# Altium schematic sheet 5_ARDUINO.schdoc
size 601 x 429 mm; Symbol: Drawing-Symbol_A4; Device: Drawing-Symbol_A4; @Project Name: Slowpoke; @Page Count: 7; @Update Date: 2025-12-15; @Create Date: 2025-12-13; @Schematic Name: Slowpoke_Sch; @Page No: 5; @Page Name: ARDUINO; Company: Analog Devices, Inc.; Version: V1.0; Page Size: A4; @Create Time: 14:28:30; @Update Time: 15:57:42; Width: 2338; Height: 1652; Region Start: 1; X Region Count: 6; Y Region Count: 4; Blade Width: 10; Title Block Position: 3; @Board Name: Slowpoke
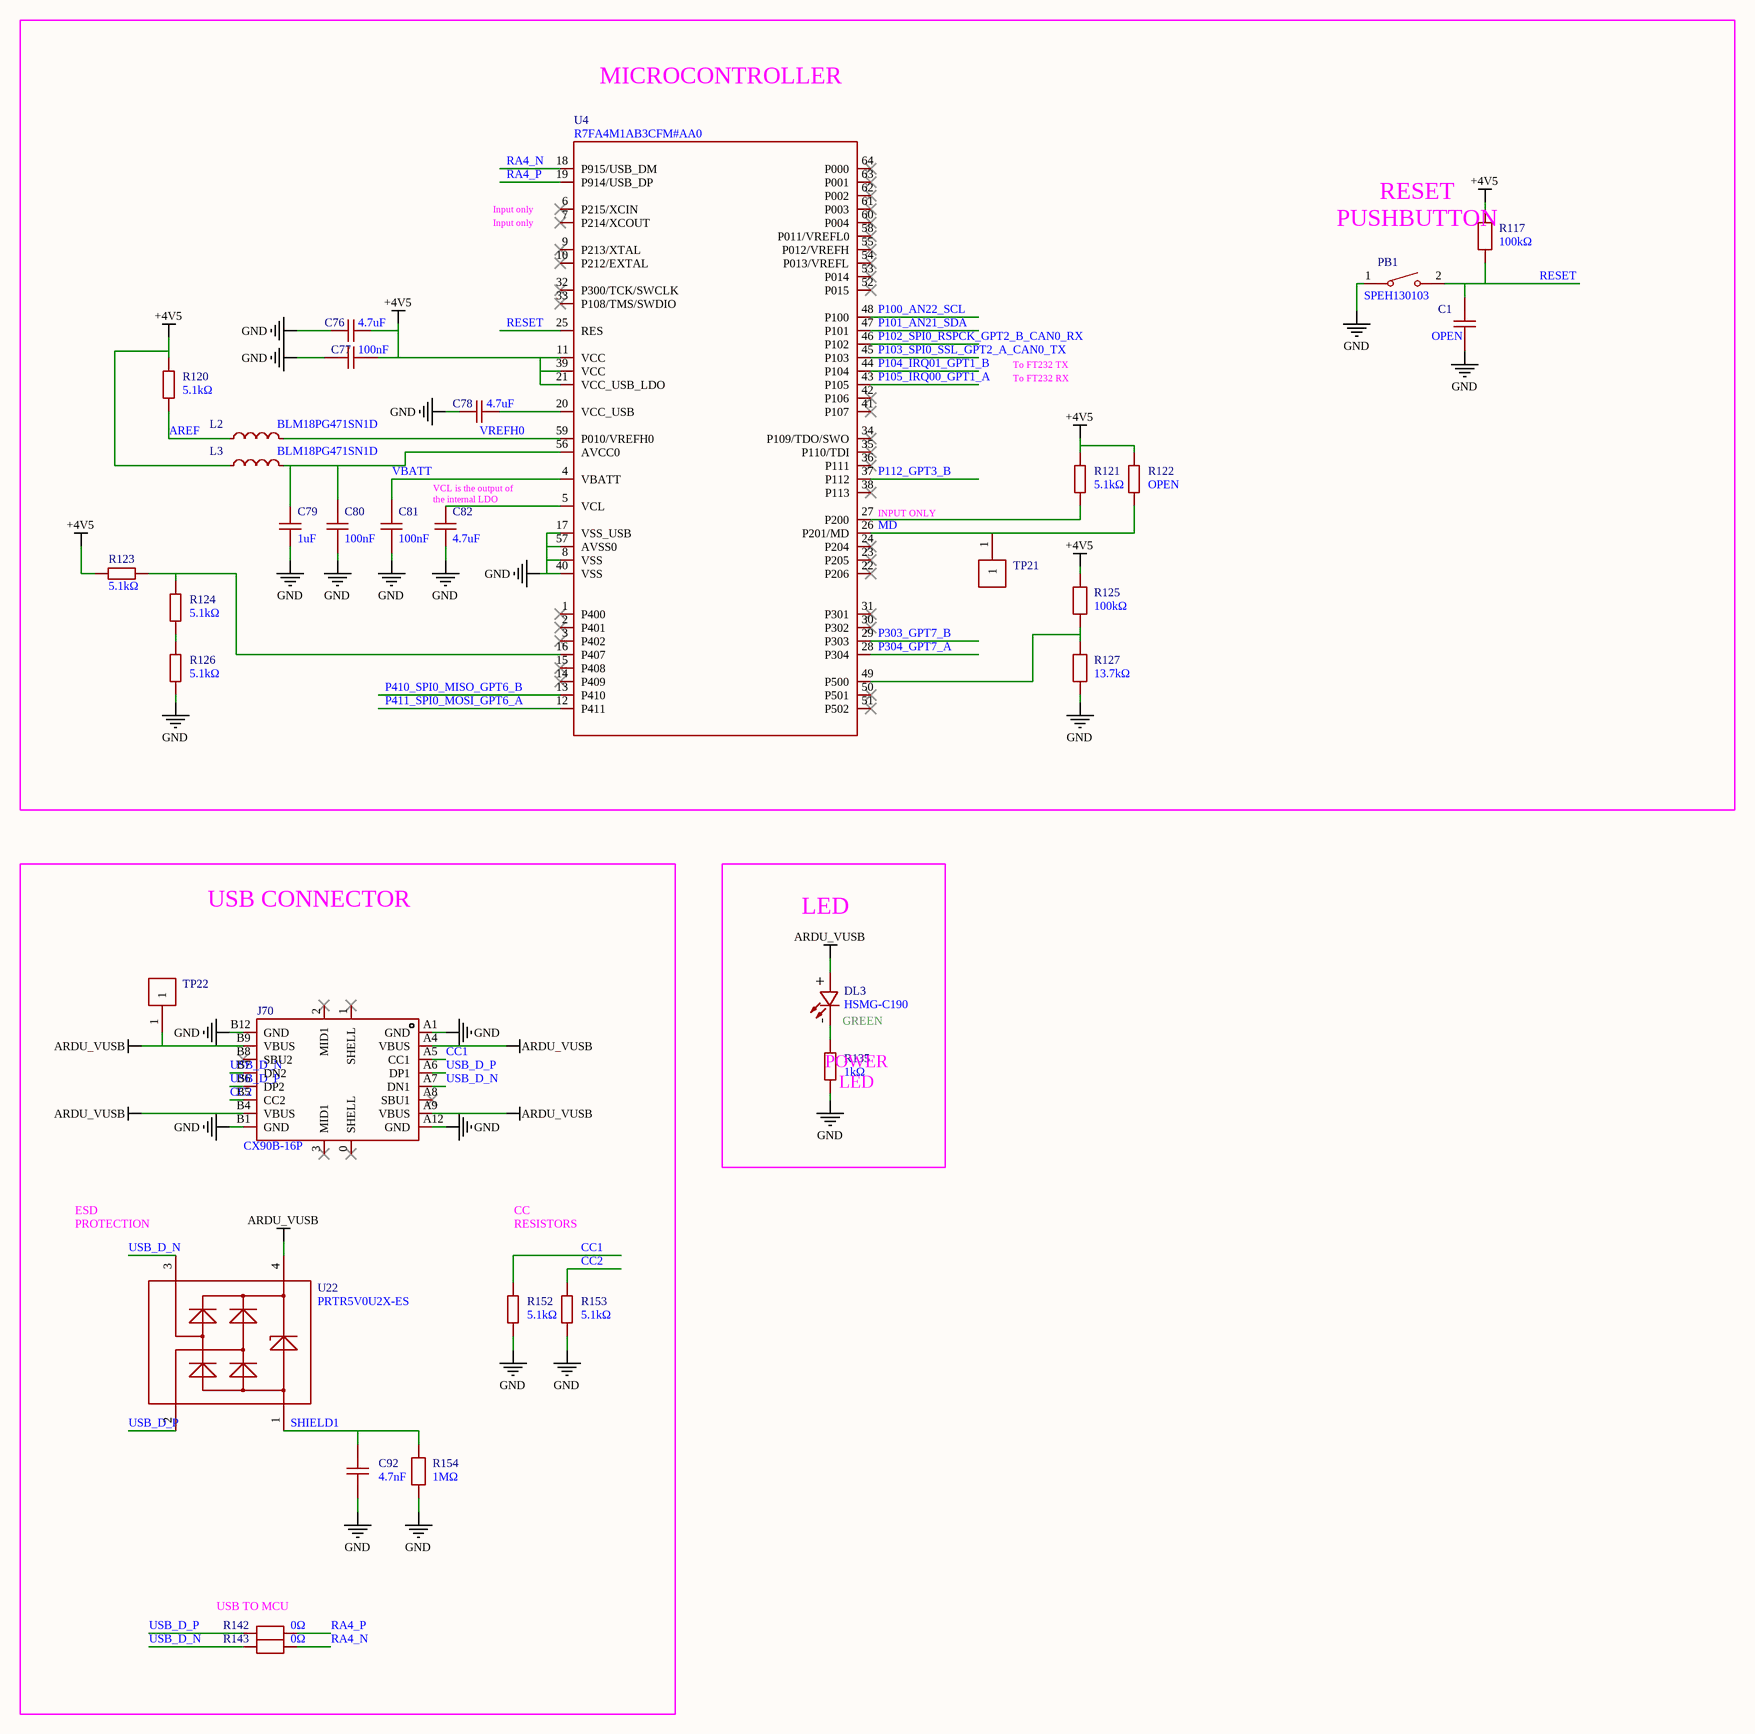
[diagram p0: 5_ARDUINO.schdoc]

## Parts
C1  OPEN  [C0402]
C76  4.7uF  [C0402]
C77  100nF  [C0402]
C78  4.7uF  [C0402]
C79  1uF  [C0402]
C80  100nF  [C0402]
C81  100nF  [C0402]
C82  4.7uF  [C0402]
C92  4.7nF  [C0805]
DL3  HSMG-C190  [LED-SMD_L1.6-W0.8-R-RD]
J70  CX90B-16P  [USB-C-SMD_CX90B-16P]
L2  BLM18PG471SN1D  [L0603]
L3  BLM18PG471SN1D  [L0603]
PB1  SPEH130103  [SW-SMD_L6.0-W6.0-LS6.6]
R117  100kΩ  [R0402]
R120  5.1kΩ  [R0402]
R121  5.1kΩ  [R0402]
R122  OPEN  [R0402]
R123  5.1kΩ  [R0402]
R124  5.1kΩ  [R0402]
R125  100kΩ  [R0402]
R126  5.1kΩ  [R0402]
R127  13.7kΩ  [R0402]
R135  1kΩ  [R0603]
R142  0Ω  [R0402]
R143  0Ω  [R0402]
R152  5.1kΩ  [R0402]
R153  5.1kΩ  [R0402]
R154  1MΩ  [R0402]
TP21  RH-5002  [TESTPOINT-TH_BD2.5-D1.2_RH-5002]  (value not drawn)
TP22  RH-5000  [TEST-TH_BD2.54-P1.4_RED]  (value not drawn)
U4  R7FA4M1AB3CFM#AA0  [LQFP-64_L10.0-W10.0-P0.50-LS12.0-BL]
U22  PRTR5V0U2X-ES  [SOT-143_L2.9-W1.3-P1.92-LS2.3-BR]

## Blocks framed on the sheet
MICROCONTROLLER: C1 C76-C82 L2 L3 PB1 R117 R120-R127 TP21 U4
USB CONNECTOR: C92 J70 R142 R143 R152-R154 TP22 U22
LED: DL3 R135

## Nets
+4V5: C76.2 C77.2 L3.1 R117.2 R120.2 R121.2 R122.2 R123.2 R125.2 U4.11(VCC) U4.21(VCC_USB_LDO) U4.39(VCC)
ARDU_VUSB: DL3.1(A) J70.A4(VBUS) J70.A9(VBUS) J70.B4(VBUS) J70.B9(VBUS) TP22.1 U22.4(VCC)
GND: C1.1 C76.1 C77.1 C78.1 C79.1 C80.1 C81.1 C82.1 C92.1 J70.A1(GND) J70.A12(GND) J70.B1(GND) J70.B12(GND) PB1.1 R126.1 R127.1 R135.1 R152.1 R153.1 R154.1 U4.8(VSS) U4.17(VSS_USB) U4.40(VSS) U4.57(AVSS0)
AREF: L2.1 R120.1
CC1: J70.A5(CC1) R152.2
CC2: J70.B5(CC2) R153.2
MD: R122.1 TP21.1 U4.26(P201/MD)
P100_AN22_SCL: U4.48(P100)
P101_AN21_SDA: U4.47(P101)
P102_SPI0_RSPCK_GPT2_B_CAN0_RX: U4.46(P102)
P103_SPI0_SSL_GPT2_A_CAN0_TX: U4.45(P103)
P104_IRQ01_GPT1_B: U4.44(P104)
P105_IRQ00_GPT1_A: U4.43(P105)
P112_GPT3_B: U4.37(P112)
P303_GPT7_B: U4.29(P303)
P304_GPT7_A: U4.28(P304)
P410_SPI0_MISO_GPT6_B: U4.13(P410)
P411_SPI0_MOSI_GPT6_A: U4.12(P411)
RA4_N: R143.2 U4.18(P915/USB_DM)
RA4_P: R142.2 U4.19(P914/USB_DP)
RESET: C1.2 PB1.2 R117.1 U4.25(RES)
SHIELD1: C92.2 R154.2 U22.1(GND)
USB_D_N: J70.A7(DN1) J70.B7(DN2) R143.1 U22.3(IO)
USB_D_P: J70.A6(DP1) J70.B6(DP2) R142.1 U22.2(IO)
VBATT: C81.2 U4.4(VBATT)
VREFH0: L2.2 U4.59(P010/VREFH0)
NetC78_2: C78.2 U4.20(VCC_USB)
NetC79_2: C79.2 C80.2 L3.2 U4.56(AVCC0)
NetC82_2: C82.2 U4.5(VCL)
NetDL3_2: DL3.2(C) R135.2
NetR121_1: R121.1 U4.27(P200)
NetR123_1: R123.1 R124.2 U4.16(P407)
NetR124_1: R124.1 R126.2
NetR125_1: R125.1 R127.2 U4.49(P500)

Not connected (* = marked no-connect by the designer): J70 0(SHELL)* 1(SHELL)* 2(MID1)* 3(MID1)* A8(SBU1)* B8(SBU2)*; U4 1(P400)* 2(P401)* 3(P402)* 6(P215/XCIN)* 7(P214/XCOUT)* 9(P213/XTAL)* 10(P212/EXTAL)* 14(P409)* 15(P408)* 22(P206)* 23(P205)* 24(P204)* 30(P302)* 31(P301)* 32(P300/TCK/SWCLK)* 33(P108/TMS/SWDIO)* 34(P109/TDO/SWO)* 35(P110/TDI)* 36(P111)* 38(P113)* 41(P107)* 42(P106)* 50(P501)* 51(P502)* 52(P015)* 53(P014)* 54(P013/VREFL)* 55(P012/VREFH)* 58(P011/VREFL0)* 60(P004)* 61(P003)* 62(P002)* 63(P001)* 64(P000)*

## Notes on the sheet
- RESET
  PUSHBUTTON
- (near U4) Input only
- To FT232 RX
- To FT232 TX
- (near C82) VCL is the output of
  the internal LDO
- (near U4) INPUT ONLY
- (near R135) POWER
  LED
- GREEN
- (near U22) ESD
  PROTECTION
- CC
  RESISTORS
- USB TO MCU

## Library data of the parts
C1 = CC0402KRX7R6BB474: Manufacturer: YAGEO(国巨); Add into BOM: yes; Tolerance: ±10%; Voltage Rating: 10V; Temperature Coefficient: X7R
C76 C78 C79 C82 = CL05A105KP5NNNC: Manufacturer: SAMSUNG(三星); Add into BOM: yes; Tolerance: ±10%; Voltage Rating: 10V; Temperature Coefficient: X5R
C77 C80 C81 = GRM155R61H104KE19D: Manufacturer: muRata(村田); Add into BOM: yes; Tolerance: ±10%
C92 = FV21X472K102ECG: Manufacturer: PSA(信昌电陶); Add into BOM: yes; Tolerance: ±10%; Voltage Rating: 1kV; Temperature Coefficient: X7R
DL3 = HSMG-C190: Manufacturer: Broadcom(博通); Add into BOM: yes; Illumination Color: Green; Voltage - Forward(Vf): 2.2V; Power(Watts): 52mW; Forward Current: 20mA; Wavelength - Dominant: 572nm; Peak Wavelength: 570nm; Luminous Intensity: 15mcd; Viewing Angle: 170°
J70 = CX90B-16P: Manufacturer: HRS(广濑); Add into BOM: yes
L2 L3 = BLM18PG471SN1D: Manufacturer: muRata(村田); Add into BOM: yes; Impedance @ Frequency: 470Ω@100MHz; Tolerance: ±25%; DC Resistance(DCR): 200mΩ; Current Rating: 1A; Number of Circuits: 1
PB1 = SPEH130103: Manufacturer: ALPSALPINE(阿尔卑斯阿尔派); Add into BOM: yes; Actuator Style: Square Button; Contact Current: 50mA; Voltage Rating: 16V; Actuator/Cap Color: Black; Operating Force: 3N
R117 = CRCW0402100KFKEDC: Manufacturer: VISHAY(威世); Add into BOM: yes; Tolerance: ±1%; Power(Watts): 62.5mW; Temperature Coefficient: ±100ppm/℃
R120-R124 R126 R152 R153 = RC0402FR-075K1L: Manufacturer: YAGEO(国巨); Add into BOM: yes; Tolerance: ±1%; Power(Watts): 62.5mW; Voltage-Supply(Max): 50V; Temperature Coefficient: ±100ppm/℃
R125 = ERA2AEB104X: Manufacturer: PANASONIC(松下); Add into BOM: yes; Tolerance: ±0.1%; Power(Watts): 63mW; Voltage-Supply(Max): 50V; Temperature Coefficient: ±25ppm/℃
R127 = RT0402BRD0713K7L: Manufacturer: YAGEO(国巨); Add into BOM: yes; Tolerance: ±0.1%; Temperature Coefficient: ±25ppm/℃
R135 = 0603WAF1001T5E: Manufacturer: UNI-ROYAL(厚声); Add into BOM: yes; Tolerance: ±1%; Power(Watts): 100mW; Voltage-Supply(Max): 75V; Temperature Coefficient: ±100ppm/℃
R142 R143 = CRCW04020000Z0EDC: Manufacturer: VISHAY(威世); Add into BOM: yes; Power(Watts): 62.5mW; Voltage-Supply(Max): 50V
R154 = CRCW04021M00FKED: Manufacturer: VISHAY(威世); Add into BOM: yes; Tolerance: ±1%; Power(Watts): 63mW; Voltage-Supply(Max): 50V; Temperature Coefficient: ±100ppm/℃
TP21 = RH-5002: Manufacturer: 荣和; Symbol: RH-5000; Add into BOM: yes; Connector Type: Pin Type (Through-Board); Plastic Color: White; Board Space (Diameter φ/ Length x Width): 2.5mm
TP22 = RH-5000: Manufacturer: 荣和; Add into BOM: yes; Connector Type: Pin Type (Through-Board); Plastic Color: Red; Board Space (Diameter φ/ Length x Width): 2.5mm
U4 = R7FA4M1AB3CFM#AA0: Manufacturer: RENESAS(瑞萨)/IDT; Add into BOM: yes; CPU Core: ARM-M4; CPU Maximum Speed: 48MHz; Program Storage Size: 256KB; Program Memory Type: FLASH; Number of I/O: 52; ADC (Bit): 14bit; DAC (Bit): 12bit；8bit; Voltage - Supply: 1.6V~5.5V
U22 = PRTR5V0U2X-ES: Manufacturer: ElecSuper(静芯); Add into BOM: yes; Polarity: Unidirectional; Reverse Stand-Off Voltage (Vrwm): 5V; Clamping Voltage: 18V; Peak Pulse Current (Ipp): 9A@8/20us; Peak Pulse Power Dissipation (Ppp): 180W@8/20us; Voltage - Breakdown: 6V; Reverse Leakage Current (Ir): 1uA; Number of Channels: 2; level of protection: IEC 61000-4-2；IEC 61000-4-4；IEC 61000-4-5; Junction Capacitance: 0.8pF；1.6pF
